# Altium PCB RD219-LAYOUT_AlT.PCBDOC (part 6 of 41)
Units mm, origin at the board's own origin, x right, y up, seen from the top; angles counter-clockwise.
Board outline 209.75 x 159.97 mm, 2 copper layers (TOP, BOTTOM), stack 0 mm thick; 398 components, 199 nets, 1469 pads, 0 vias.
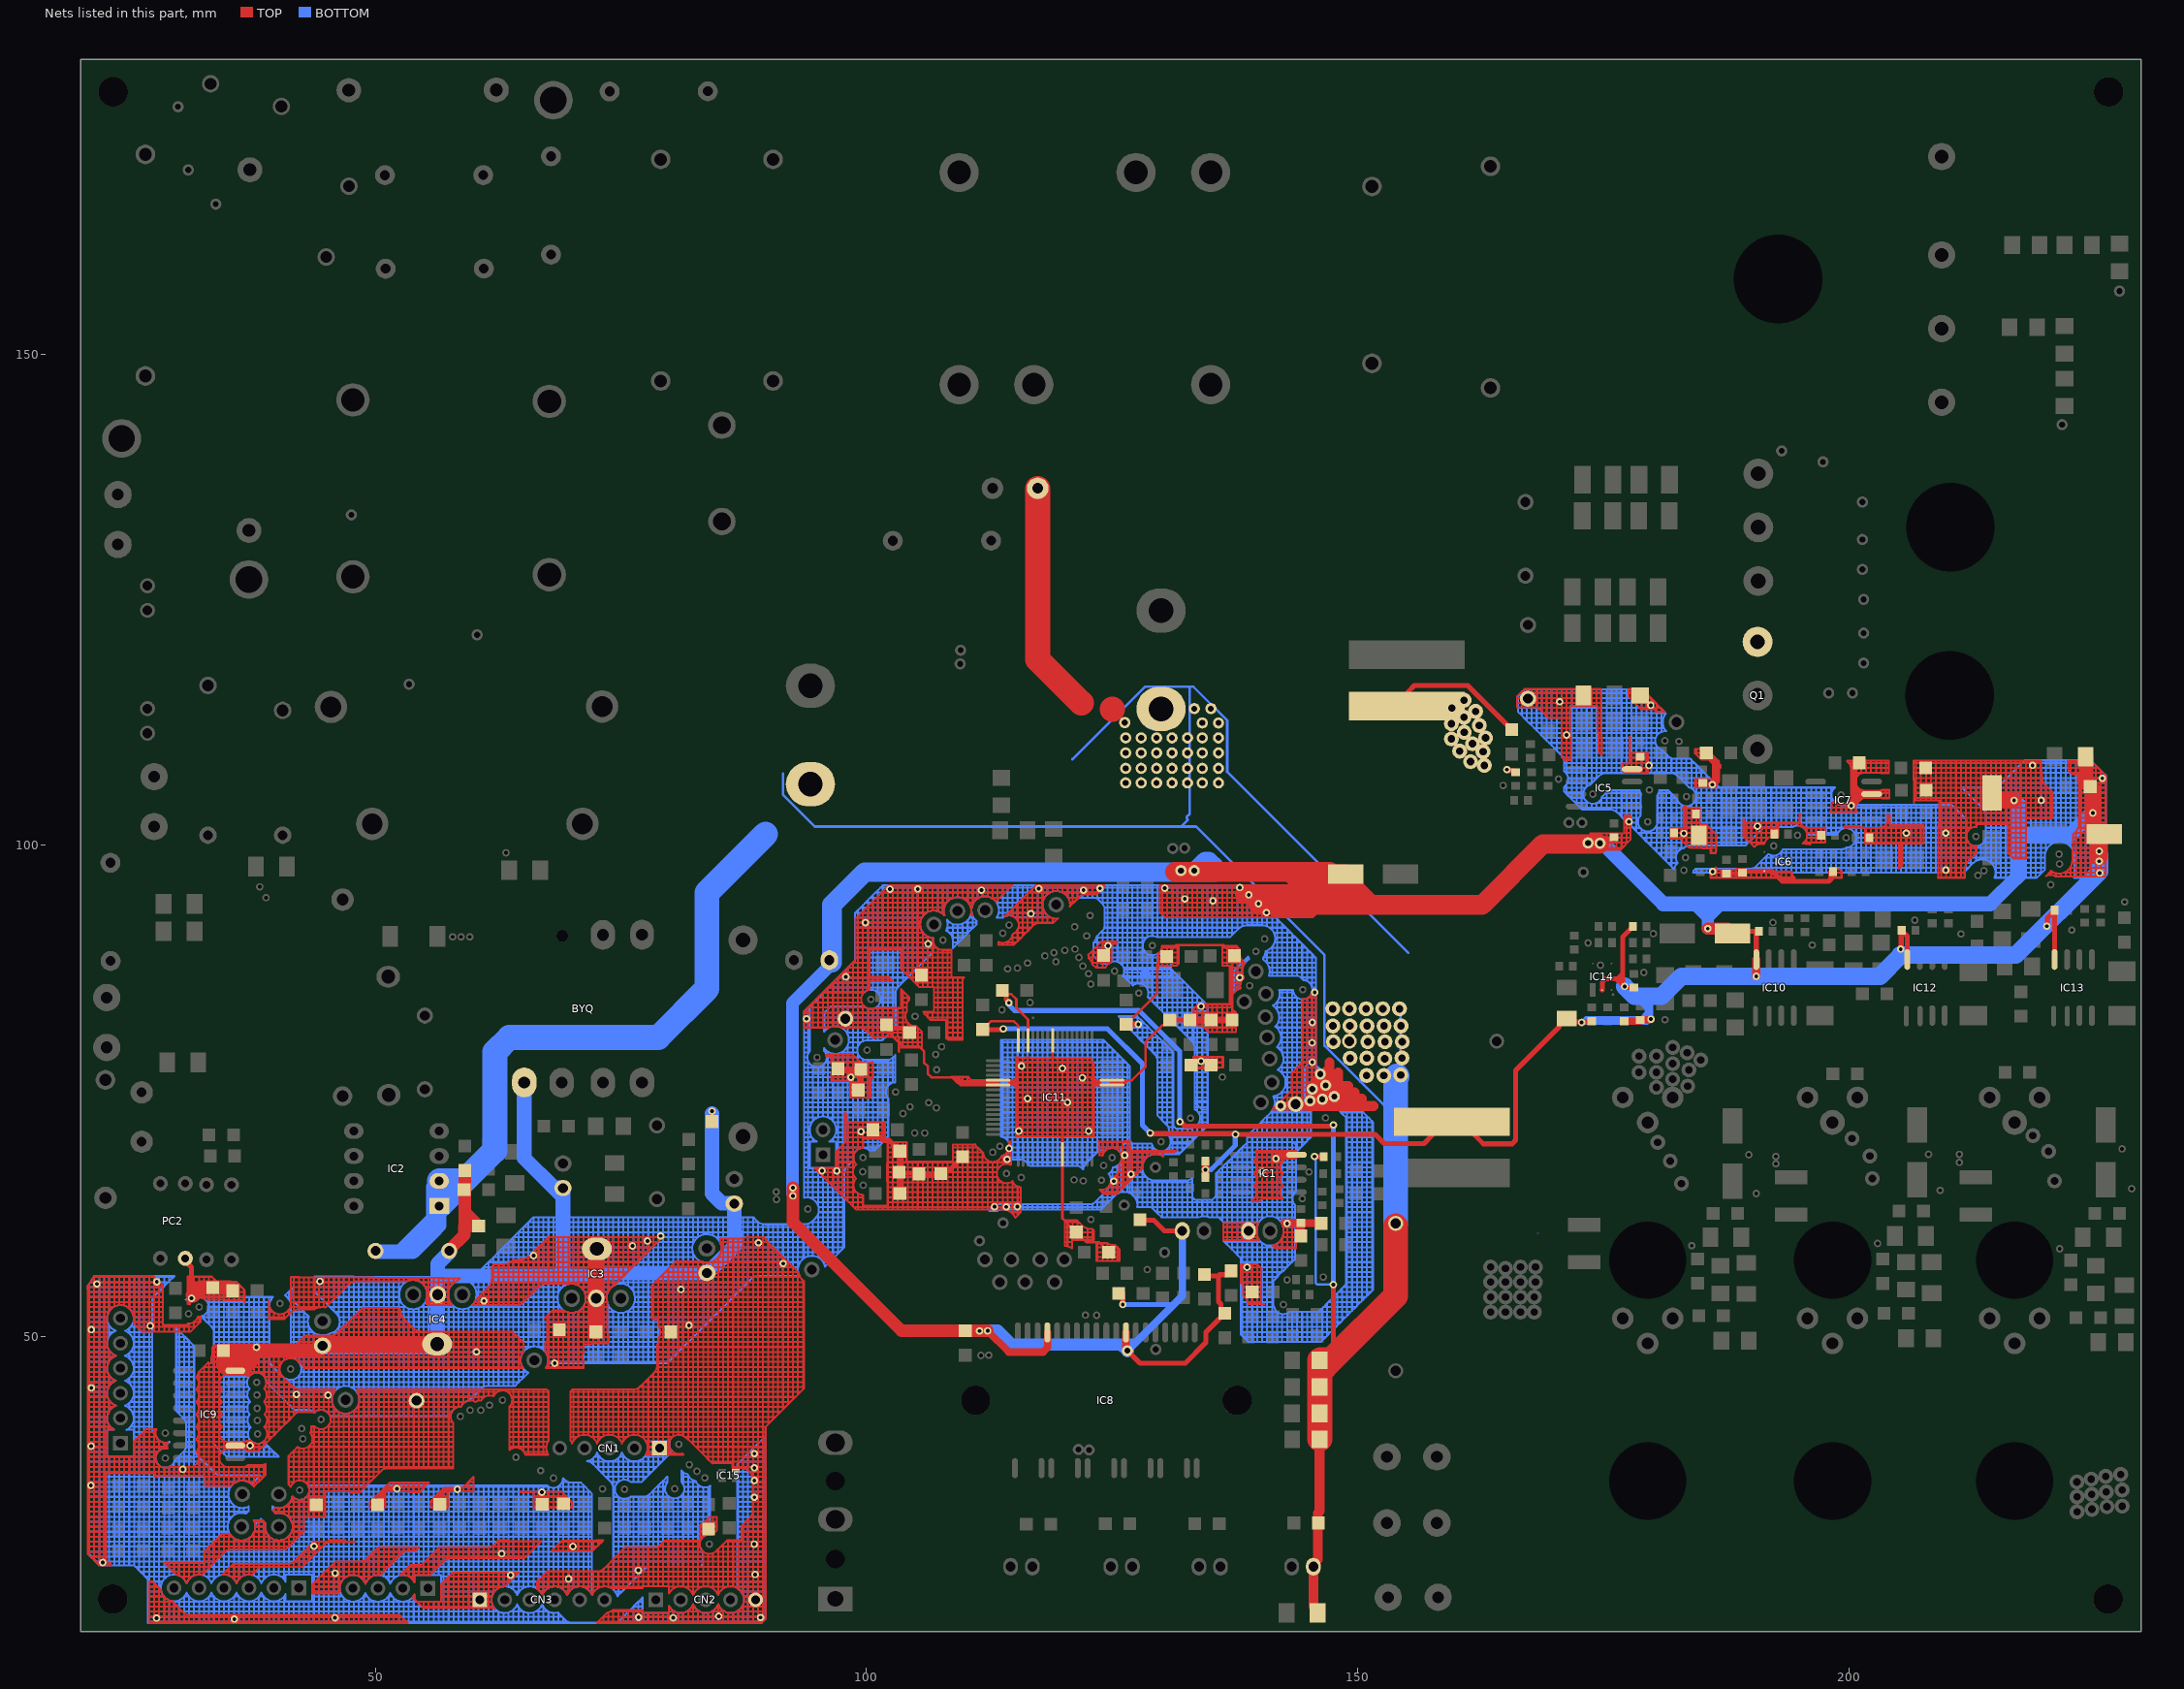
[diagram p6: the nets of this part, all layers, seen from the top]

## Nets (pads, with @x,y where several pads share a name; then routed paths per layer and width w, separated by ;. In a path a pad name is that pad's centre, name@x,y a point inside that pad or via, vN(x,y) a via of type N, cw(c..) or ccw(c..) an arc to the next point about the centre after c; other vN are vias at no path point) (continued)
GND: (continued)
  TOP w0.203: 42.225,33.41 ccw(c42.307,34.389) 42.307,33.407 ccw(c42.307,34.389) 42.733,33.504 ; 42.225,35.368 cw(c42.307,34.389) 42.733,35.275 ; 42.225,35.368 42.225,35.748 ; 42.225,35.748 42.225,36.256 ; 42.225,35.748 42.733,35.748 ; 42.225,36.256 42.733,36.256 ; 42.225,36.256 42.225,36.764 ; 42.225,36.764 42.733,36.764 ; 42.225,36.764 42.225,37.272 ; 42.225,37.272 42.225,37.78 ; 42.225,37.272 42.733,37.272 ; 42.225,37.78 42.225,38.288 ; 42.225,37.78 42.733,37.78 ; 42.225,38.288 42.733,38.288 ; 42.225,38.288 42.225,38.712 ; 42.225,38.712 ccw(c42.625,39.609) 42.728,38.632 ccw(c42.625,39.609) 42.733,38.632 ; 42.225,42.332 cw(c42.376,41.62) 42.376,42.348 ; 42.225,42.332 cw(c42.376,41.62) 42.376,42.348 ; 42.225,42.332 42.225,42.352 ; 42.225,42.352 42.225,42.86 ; 42.225,42.352 42.733,42.352 ; 42.225,42.86 42.225,43.368 ; 42.225,42.86 42.733,42.86 ; 42.225,43.368 pad.@42.225,43.876 ; 42.225,43.368 42.733,43.368 ; pad.@42.225,43.876 42.733,43.876 ; pad.@42.225,43.876 pad.@42.225,44.384 ; pad.@42.225,44.384 42.733,44.384 ; pad.@42.225,44.384 42.225,44.643 ; 42.225,44.643 ccw(c42.354,45.737) 42.354,44.635 ; 42.225,44.643 ccw(c42.354,45.737) 42.354,44.635 ; 42.225,47.423 42.225,47.432 ; 42.225,47.423 42.724,46.924 ; 42.225,47.432 42.225,47.94 ; 42.225,47.432 42.733,47.432 ; 42.225,47.94 42.225,48.448 ; 42.225,47.94 42.733,47.94 ; 42.225,48.448 42.225,48.575 42.225,48.956 ; 42.225,48.448 42.733,48.448 ; 42.225,48.956 42.733,48.956 ; 42.225,48.956 42.225,49.46 ; 42.225,49.46 ccw(c41.322,50.466) 42.229,49.464 ; 42.225,49.46 ccw(c41.322,50.466) 42.229,49.464 ; 42.225,52.805 cw(c42.312,51.456) 42.312,52.808 ; 42.225,52.805 cw(c42.312,51.456) 42.312,52.808 ; 42.225,52.805 42.225,53.02 ; 42.225,53.02 42.225,53.528 ; 42.225,53.02 42.733,53.02 ; 42.225,53.528 42.225,54.036 ; 42.225,53.528 42.733,53.528 ; 42.225,54.036 42.225,54.544 ; 42.225,54.036 42.733,54.036 ; 42.225,54.544 42.225,55.052 ; 42.225,54.544 42.733,54.544 ; 42.225,55.052 42.225,55.56 ; 42.225,55.052 42.733,55.052 ; 42.225,55.56 42.225,56.059 ; 42.225,55.56 42.733,55.56 ; 42.225,56.059 42.733,56.056 ; 42.229,49.464 ccw(c41.322,50.466) 42.277,49.51 cw(c41.322,50.466) 42.229,49.464 ; 42.229,49.464 42.733,49.464 ; 42.239,27.62 42.747,28.128 ; 42.239,27.62 42.733,27.62 ; 42.312,52.808 42.733,52.808 ; 42.354,44.635 42.733,44.635 ; 42.376,42.348 42.733,42.348 ; 42.724,46.924 42.733,46.915 ; 42.724,46.924 42.733,46.924 ; 42.733,20.889 42.733,21.016 ; 42.733,20.889 43.241,20.889 ; 42.733,21.016 42.733,21.524 ; 42.733,21.016 43.241,21.016 ; 42.733,21.524 42.733,21.692 ; 42.733,21.524 43.241,21.524 ; 42.733,21.692 43.241,21.692 ; 42.733,27.112 42.733,27.62 ; 42.733,27.62 43.241,27.62 ; 42.733,30.174 42.733,30.668 ; 42.733,30.174 42.751,30.193 42.751,30.668 ; 42.733,30.668 42.733,31.176 ; 42.733,30.668 42.751,30.668 ; 42.733,31.176 42.733,31.684 ; 42.733,31.176 42.751,31.176 ; 42.733,31.684 43.241,31.684 ; 42.733,31.684 42.733,32.192 ; 42.733,32.192 43.241,32.192 ; 42.733,32.192 42.733,32.7 ; 42.733,32.7 42.733,33.208 ; 42.733,32.7 43.241,32.7 ; 42.733,33.208 43.241,33.208 ; 42.733,33.208 42.733,33.504 ; 42.733,33.504 ccw(c42.307,34.389) 43.023,33.716 ; 42.733,35.275 cw(c42.307,34.389) 42.799,35.24 ; 42.733,35.275 42.733,35.748 ; 42.733,35.748 42.733,36.256 ; 42.733,35.748 43.241,35.748 ; 42.733,36.256 42.733,36.764 ; 42.733,36.256 43.241,36.256 ; 42.733,36.764 42.733,37.272 ; 42.733,36.764 43.241,36.764 ; 42.733,37.272 42.733,37.78 ; 42.733,37.272 43.241,37.272 ; 42.733,37.78 42.733,38.288 ; 42.733,37.78 43.241,37.78 ; 42.733,38.288 43.241,38.288 ; 42.733,38.288 42.733,38.632 ; 42.733,38.632 ccw(c42.625,39.609) 43.177,38.796 ; 42.733,42.348 42.733,42.352 ; 42.733,42.348 43.241,42.348 ; 42.733,42.352 42.733,42.86 ; 42.733,42.352 43.241,42.352 ; 42.733,42.86 42.733,43.368 ; 42.733,42.86 43.241,42.86 ; 42.733,43.368 42.733,43.876 ; 42.733,43.368 43.241,43.368 ; 42.733,43.876 42.733,44.384 ; 42.733,43.876 43.241,43.876 ; 42.733,44.384 42.733,44.635 ; 42.733,44.384 43.241,44.384 ; 42.733,44.635 43.241,44.635 ; 42.733,46.915 42.733,46.924 ; 42.733,46.915 42.81,46.838 43.241,46.838 ; 42.733,46.924 42.733,47.432 ; 42.733,46.924 43.241,46.924 ; 42.733,47.432 42.733,47.94 ; 42.733,47.432 43.241,47.432 ; 42.733,47.94 42.733,48.448 ; 42.733,47.94 43.241,47.94 ; 42.733,48.448 42.733,48.575 42.733,48.956 ; 42.733,48.448 43.241,48.448 ; 42.733,48.956 42.733,49.464 ; 42.733,48.956 43.241,48.956 ; 42.733,49.464 43.241,49.464 ; 42.733,52.808 42.733,53.02 ; 42.733,52.808 43.241,52.808 ; 42.733,53.02 42.733,53.528 ; 42.733,53.02 43.241,53.02 ; 42.733,53.528 42.733,54.036 ; 42.733,53.528 43.241,53.528 ; 42.733,54.036 42.733,54.544 ; 42.733,54.036 43.241,54.036 ; 42.733,54.544 42.733,55.052 ; 42.733,54.544 43.241,54.544 ; 42.733,55.052 42.733,55.56 ; 42.733,55.052 43.241,55.052 ; 42.733,55.56 42.733,56.056 ; 42.733,55.56 43.241,55.56 ; 42.733,56.056 43.241,56.052 ; 42.739,49.972 42.872,50.104 43.241,50.104 ; 42.739,49.972 43.241,49.972 ; 42.747,28.128 43.255,28.636 ; 42.747,28.128 43.241,28.128 ; 42.751,30.668 42.751,31.176 ; 42.751,31.176 42.751,31.666 43.241,31.666 ; 42.799,35.24 cw(c42.307,34.389) 43.228,34.732 ; 42.799,35.24 43.241,35.24 ; 43.023,33.716 ccw(c42.307,34.389) 43.026,33.719 ccw(c42.307,34.389) 43.241,34.083 ; 43.023,33.716 43.241,33.716 ; 43.177,38.796 ccw(c42.625,39.609) 43.241,38.843 ; 43.177,38.796 43.241,38.796 ; 43.228,34.732 cw(c42.307,34.389) 43.241,34.695 ; 43.228,34.732 43.241,34.732 ; 43.241,20.889 43.241,21.016 ; 43.241,20.889 43.749,20.889 ; 43.241,21.016 43.241,21.524 ; 43.241,21.016 43.749,21.016 ; 43.241,21.524 43.241,21.692 ; 43.241,21.524 43.749,21.524 ; 43.241,21.692 43.749,21.692 ; 43.241,27.62 43.241,28.128 ; 43.241,28.128 43.749,28.128 ; 43.241,31.666 43.749,31.666 ; 43.241,31.666 43.241,31.684 ; 43.241,31.684 43.749,31.684 ; 43.241,31.684 43.241,32.192 ; 43.241,32.192 43.749,32.192 ; 43.241,32.192 43.241,32.7 ; 43.241,32.7 43.241,33.208 ; 43.241,32.7 R72.1@43.749,32.7 ; 43.241,33.208 43.241,33.716 ; 43.241,33.208 R72.1@43.749,33.208 ; 43.241,33.716 43.749,33.716 ; 43.241,33.716 43.241,34.083 ; 43.241,34.083 ccw(c42.307,34.389) 43.276,34.224 ; 43.241,34.695 cw(c42.307,34.389) 43.242,34.693 cw(c42.307,34.389) 43.29,34.389 cw(c42.307,34.389) 43.276,34.224 ; 43.241,34.695 43.241,34.732 ; 43.241,34.732 43.749,34.732 ; 43.241,34.732 43.241,35.24 ; 43.241,35.24 43.241,35.748 ; 43.241,35.24 43.749,35.24 ; 43.241,35.748 43.241,36.256 ; 43.241,35.748 43.749,35.748 ; 43.241,36.256 43.749,36.256 ; 43.241,36.256 43.241,36.764 ; 43.241,36.764 43.749,36.764 ; 43.241,36.764 43.241,37.272 ; 43.241,37.272 43.241,37.78 ; 43.241,37.272 43.749,37.272 ; 43.241,37.78 43.749,37.78 ; 43.241,37.78 43.241,38.288 ; 43.241,38.288 43.241,38.796 ; 43.241,38.288 43.749,38.288 ; 43.241,38.796 43.749,38.796 ; 43.241,38.796 43.241,38.843 ; 43.241,38.843 ccw(c42.625,39.609) 43.244,38.845 ccw(c42.625,39.609) 43.559,39.304 ; 43.241,42.348 43.749,42.348 ; 43.241,42.348 43.241,42.352 ; 43.241,42.352 43.749,42.352 ; 43.241,42.352 43.241,42.86 ; 43.241,42.86 43.749,42.86 ; 43.241,42.86 43.241,43.368 ; 43.241,43.368 43.749,43.368 ; 43.241,43.368 43.241,43.876 ; 43.241,43.876 43.749,43.876 ; 43.241,43.876 43.241,44.384 ; 43.241,44.384 43.749,44.384 ; 43.241,44.384 43.241,44.635 ; 43.241,44.635 43.749,44.635 ; 43.241,46.838 43.241,46.924 ; 43.241,46.838 43.749,46.838 ; 43.241,46.924 43.241,47.432 ; 43.241,46.924 43.749,46.924 ; 43.241,47.432 43.241,47.94 ; 43.241,47.432 43.749,47.432 ; 43.241,47.94 43.241,48.448 ; 43.241,47.94 43.749,47.94 ; 43.241,48.448 43.241,48.575 43.241,48.956 ; 43.241,48.448 43.749,48.448 ; 43.241,48.956 43.241,49.464 ; 43.241,48.956 43.749,48.956 ; 43.241,49.464 43.241,49.972 ; 43.241,49.464 43.749,49.464 ; 43.241,49.972 43.241,50.104 ; 43.241,49.972 43.749,49.972 ; 43.241,50.104 43.749,50.104 ; 43.241,52.808 43.749,52.808 ; 43.241,52.808 43.241,53.02 ; 43.241,53.02 43.749,53.02 ; 43.241,53.02 43.241,53.528 ; 43.241,53.528 43.749,53.528 ; 43.241,53.528 43.241,54.036 ; 43.241,54.036 43.241,54.544 ; 43.241,54.036 43.749,54.036 ; 43.241,54.544 43.241,55.052 ; 43.241,54.544 43.749,54.544 ; 43.241,55.052 43.241,55.56 ; 43.241,55.052 43.749,55.052 ; 43.241,55.56 43.241,56.052 ; 43.241,55.56 43.749,55.56 ; 43.241,56.052 43.749,56.049 ; 43.255,28.636 pad.@43.749,28.636 ; 43.255,28.636 43.763,29.144 ; 43.276,34.224 43.749,34.224 ; 43.435,40.32 ccw(c42.513,40.658) 43.48,40.828 ; 43.435,40.32 43.749,40.32 ; 43.467,40.891 cw(c42.513,40.658) 43.48,40.828 ; 43.467,40.891 43.749,40.891 ; 43.48,40.828 43.749,40.828 ; 43.559,39.304 ccw(c42.625,39.609) 43.56,39.305 ccw(c42.625,39.609) 43.608,39.609 ccw(c42.625,39.609) 43.587,39.812 ; 43.559,39.304 43.749,39.304 ; 43.577,24.064 43.749,24.064 ; 43.577,24.064 43.577,24.572 ; 43.577,24.064 43.577,23.896 43.749,23.896 ; 43.577,24.572 43.749,24.572 ; 43.577,24.572 43.577,24.766 43.749,24.939 ; 43.587,39.812 43.749,39.812 ; 43.749,20.889 43.749,21.016 ; 43.749,20.889 44.257,20.889 ; 43.749,21.016 43.749,21.524 ; 43.749,21.016 44.257,21.016 ; 43.749,21.524 43.749,21.692 ; 43.749,21.524 44.257,21.524 ; 43.749,21.692 44.257,21.692 ; 43.749,23.896 43.749,24.064 ; 43.749,23.896 44.257,23.896 ; 43.749,24.064 43.749,24.572 ; 43.749,24.064 44.257,24.064 ; 43.749,24.572 43.749,24.939 ; 43.749,24.572 44.257,24.572 ; 43.749,24.939 43.89,25.08 ; 43.749,28.128 pad.@43.749,28.636 ; pad.@43.749,28.636 44.257,28.636 ; 43.749,31.666 44.257,31.666 ; 43.749,31.666 43.749,31.684 ; 43.749,31.684 44.257,31.684 ; 43.749,31.684 43.749,32.192 ; 43.749,32.192 R72.1@43.749,32.7 ; 43.749,32.192 44.257,32.192 ; R72.1@43.749,32.7 R72.1@44.257,32.7 ; R72.1@43.749,32.7 R72.1@43.749,33.208 ; R72.1@43.749,33.208 43.749,33.716 ; R72.1@43.749,33.208 R72.1@44.257,33.208 ; 43.749,33.716 43.749,34.224 ; 43.749,33.716 44.257,33.716 ; 43.749,34.224 44.257,34.224 ; 43.749,34.224 43.749,34.732 ; 43.749,34.732 43.749,35.24 ; 43.749,34.732 44.257,34.732 ; 43.749,35.24 43.749,35.748 ; 43.749,35.24 44.257,35.24 ; 43.749,35.748 43.749,36.256 ; 43.749,35.748 44.257,35.748 ; 43.749,36.256 44.257,36.256 ; 43.749,36.256 43.749,36.764 ; 43.749,36.764 44.257,36.764 ; 43.749,36.764 43.749,37.272 ; 43.749,37.272 43.749,37.78 ; 43.749,37.272 44.257,37.272 ; 43.749,37.78 43.749,38.288 ; 43.749,37.78 44.257,37.78 ; 43.749,38.288 43.749,38.796 ; 43.749,38.288 44.257,38.288 ; 43.749,38.796 43.749,39.304 ; 43.749,38.796 44.257,38.796 ; 43.749,39.304 43.749,39.812 ; 43.749,39.304 44.257,39.304 ; 43.749,39.812 43.749,40.32 ; 43.749,39.812 44.257,39.812 ; 43.749,40.32 44.257,40.32 ; 43.749,40.32 43.749,40.828 ; 43.749,40.828 43.749,40.891 ; 43.749,40.828 43.862,40.828 ; 43.749,40.891 43.792,40.891 ; 43.749,42.348 43.749,42.352 ; 43.749,42.352 43.749,42.86 ; 43.749,42.86 43.749,43.368 ; 43.749,42.86 44.257,42.86 ; 43.749,43.368 43.749,43.876 ; 43.749,43.368 44.257,43.368 ; 43.749,43.876 44.257,43.876 ; 43.749,43.876 43.749,44.384 ; 43.749,44.384 44.257,44.384 ; 43.749,44.384 43.749,44.635 ; 43.749,44.635 44.257,44.635 ; 43.749,46.838 43.749,46.924 ; 43.749,46.838 44.257,46.838 ; 43.749,46.924 43.749,47.432 ; 43.749,46.924 44.257,46.924 ; 43.749,47.432 43.749,47.94 ; 43.749,47.432 44.257,47.432 ; 43.749,47.94 43.749,48.448 ; 43.749,47.94 44.257,47.94 ; 43.749,48.448 43.749,48.575 43.749,48.956 ; 43.749,48.448 EC6.2@44.257,48.448 ; 43.749,48.956 EC6.2@44.257,48.956 ; 43.749,48.956 43.749,49.464 ; 43.749,49.464 43.749,49.972 ; 43.749,49.464 EC6.2@44.257,49.464 ; 43.749,49.972 43.749,50.104 ; 43.749,49.972 44.257,49.972 ; 43.749,50.104 44.257,50.104 ; 43.749,52.808 43.749,53.02 ; 43.749,52.808 43.842,52.808 ; 43.749,53.02 44.257,53.02 ; 43.749,53.02 43.749,53.528 ; 43.749,53.528 44.257,53.528 ; 43.749,53.528 43.749,54.036 ; 43.749,54.036 43.749,54.544 ; 43.749,54.036 44.257,54.036 ; 43.749,54.544 43.749,55.052 ; 43.749,54.544 44.257,54.544 ; 43.749,55.052 43.749,55.56 ; 43.749,55.052 44.257,55.052 ; 43.749,55.56 43.749,56.049 ; 43.749,55.56 pad.@44.257,55.56 ; 43.749,56.049 44.257,56.046 ; 43.763,29.144 43.782,29.162 44.257,29.162 ; 43.763,29.144 44.257,29.144 ; 43.792,40.891 ccw(c44.482,41.59) 43.862,40.828 ; 43.842,52.808 cw(c44.575,51.583) 44.253,52.974 cw(c44.575,51.583) 44.257,52.974 ; 43.89,25.08 44.257,25.447 ; 43.89,25.08 44.257,25.08 ; 44.257,20.889 44.257,21.016 ; 44.257,20.889 44.765,20.889 ; 44.257,21.016 44.257,21.524 ; 44.257,21.016 44.765,21.016 ; 44.257,21.524 44.257,21.692 ; 44.257,21.524 44.765,21.524 ; 44.257,21.692 44.765,21.692 ; 44.257,23.896 44.257,24.064 ; 44.257,23.896 44.765,23.896 ; 44.257,24.064 44.257,24.572 ; 44.257,24.064 44.765,24.064 ; 44.257,24.572 44.257,25.08 ; 44.257,24.572 44.765,24.572 ; 44.257,25.08 44.257,25.447 ; 44.257,25.08 44.765,25.08 ; 44.257,25.447 44.398,25.588 ; 44.257,28.636 44.257,29.144 ; 44.257,29.144 44.765,29.144 ; 44.257,29.144 44.257,29.162 ; 44.257,29.162 44.765,29.162 ; 44.257,31.666 44.765,31.666 ; 44.257,31.666 44.257,31.684 ; 44.257,31.684 44.765,31.684 ; 44.257,31.684 44.257,32.192 ; 44.257,32.192 44.765,32.192 ; 44.257,32.192 R72.1@44.257,32.7 ; R72.1@44.257,32.7 44.765,32.7 ; R72.1@44.257,32.7 R72.1@44.257,33.208 ; R72.1@44.257,33.208 44.257,33.716 ; R72.1@44.257,33.208 44.765,33.208 ; 44.257,33.716 44.257,34.224 ; 44.257,33.716 44.765,33.716 ; 44.257,34.224 44.765,34.224 ; 44.257,34.224 44.257,34.732 ; 44.257,34.732 44.257,35.24 ; 44.257,34.732 44.765,34.732 ; 44.257,35.24 44.257,35.748 ; 44.257,35.24 44.765,35.24 ; 44.257,35.748 44.257,36.256 ; 44.257,35.748 44.765,35.748 ; 44.257,36.256 44.765,36.256 ; 44.257,36.256 44.257,36.764 ; 44.257,36.764 44.765,36.764 ; 44.257,36.764 44.257,37.272 ; 44.257,37.272 44.257,37.78 ; 44.257,37.272 44.765,37.272 ; 44.257,37.78 44.765,37.78 ; 44.257,37.78 44.257,38.288 ; 44.257,38.288 44.257,38.796 ; 44.257,38.288 44.765,38.288 ; 44.257,38.796 44.257,39.304 ; 44.257,38.796 44.765,38.796 ; 44.257,39.304 44.257,39.812 ; 44.257,39.304 44.765,39.304 ; 44.257,39.812 44.257,40.32 ; 44.257,39.812 44.765,39.812 ; 44.257,40.32 44.765,40.32 ; 44.257,42.546 cw(c44.482,41.59) 44.261,42.547 cw(c44.482,41.59) 44.765,42.531 ; 44.257,42.546 44.257,42.86 ; 44.257,42.86 44.257,43.368 ; 44.257,42.86 44.765,42.86 ; 44.257,43.368 44.257,43.876 ; 44.257,43.368 44.765,43.368 ; 44.257,43.876 44.257,44.384 ; 44.257,43.876 44.765,43.876 ; 44.257,44.384 44.257,44.635 ; 44.257,44.384 44.765,44.384 ; 44.257,44.635 44.765,44.635 ; 44.257,46.838 44.257,46.924 ; 44.257,46.838 44.765,46.838 ; 44.257,46.924 44.257,47.432 ; 44.257,46.924 44.765,46.924 ; 44.257,47.432 44.257,47.94 ; 44.257,47.432 44.765,47.432 ; 44.257,47.94 EC6.2@44.257,48.448 ; 44.257,47.94 44.765,47.94 ; EC6.2@44.257,48.448 44.257,48.806 EC6.2@44.257,48.956 ; EC6.2@44.257,48.448 EC6.2@44.765,48.448 ; EC6.2@44.257,48.956 44.407,48.956 EC6.2@44.765,48.956 ; EC6.2@44.257,48.956 EC6.2@44.257,49.464 ; EC6.2@44.257,49.464 44.257,49.972 ; EC6.2@44.257,49.464 EC6.2@44.765,49.464 ; 44.257,49.972 44.257,50.104 ; 44.257,49.972 44.765,49.972 ; 44.257,50.104 44.765,50.104 ; 44.257,52.974 cw(c44.575,51.583) 44.575,53.01 44.702,53.01 cw(c44.702,51.583) 44.765,53.009 ; 44.257,52.974 44.257,53.02 ; 44.257,53.02 44.765,53.02 ; 44.257,53.02 44.257,53.528 ; 44.257,53.528 44.765,53.528 ; 44.257,53.528 44.257,54.036 ; 44.257,54.036 44.257,54.544 ; 44.257,54.036 44.765,54.036 ; 44.257,54.544 44.257,55.052 ; 44.257,54.544 44.765,54.544 ; 44.257,55.052 pad.@44.257,55.56 ; 44.257,55.052 44.765,55.052 ; pad.@44.257,55.56 44.257,56.046 ; pad.@44.257,55.56 44.765,55.56 ; 44.257,56.046 44.37,56.045 44.765,56.042 ; 44.398,25.588 44.765,25.588 ; 44.398,25.588 44.765,25.955 ; 44.765,20.889 44.765,21.016 ; 44.765,20.889 45.273,20.889 ; 44.765,21.016 44.765,21.524 ; 44.765,21.016 45.273,21.016 ; 44.765,21.524 44.765,21.692 ; 44.765,21.524 45.273,21.524 ; 44.765,21.692 45.273,21.692 ; 44.765,23.896 44.765,24.064 ; 44.765,23.896 45.273,23.896 ; 44.765,24.064 44.765,24.572 ; 44.765,24.064 45.273,24.064 ; 44.765,24.572 44.765,25.08 ; 44.765,24.572 45.273,24.572 ; 44.765,25.08 44.765,25.588 ; 44.765,25.08 45.273,25.08 ; 44.765,25.588 44.765,25.955 ; 44.765,25.588 45.273,25.588 ; 44.765,25.955 44.906,26.096 ; 44.765,28.777 44.765,29.144 ; 44.765,28.777 44.885,28.897 ; 44.765,29.144 45.273,29.144 ; 44.765,29.144 44.765,29.162 ; 44.765,29.162 45.255,29.162 45.255,29.289 45.273,29.289 ; 44.765,31.666 44.91,31.666 44.91,31.684 ; 44.765,31.666 44.765,31.684 ; 44.765,31.684 44.765,32.192 ; 44.765,31.684 44.91,31.684 ; 44.765,32.192 44.91,32.192 ; 44.765,32.192 44.765,32.7 ; 44.765,32.7 44.765,33.208 ; 44.765,32.7 44.91,32.7 ; 44.765,33.208 44.765,33.716 ; 44.765,33.208 44.91,33.208 ; 44.765,33.716 44.765,34.224 ; 44.765,33.716 44.91,33.716 ; 44.765,34.224 44.91,34.224 ; 44.765,34.224 44.765,34.732 ; 44.765,34.732 44.765,35.24 ; 44.765,34.732 45.273,34.732 ; 44.765,35.24 44.765,35.748 ; 44.765,35.24 45.273,35.24 ; 44.765,35.748 44.765,36.256 ; 44.765,35.748 45.273,35.748 ; 44.765,36.256 45.273,36.256 ; 44.765,36.256 44.765,36.764 ; 44.765,36.764 45.273,36.764 ; 44.765,36.764 44.765,37.272 ; 44.765,37.272 44.765,37.78 ; 44.765,37.272 45.273,37.272 ; 44.765,37.78 44.765,38.288 ; 44.765,37.78 45.273,37.78 ; 44.765,38.288 44.765,38.796 ; 44.765,38.288 45.273,38.288 ; 44.765,38.796 44.765,39.304 ; 44.765,38.796 45.273,38.796 ; 44.765,39.304 44.765,39.812 ; 44.765,39.304 45.273,39.304 ; 44.765,39.812 44.765,40.32 ; 44.765,39.812 45.273,39.812 ; 44.765,40.32 45.273,40.32 ; 44.765,40.32 44.765,40.649 ; 44.765,40.649 ccw(c44.482,41.59) 45.101,40.826 ccw(c44.482,41.59) 45.103,40.828 ; 44.765,42.531 44.765,42.86 ; 44.765,42.86 44.765,43.368 ; 44.765,42.86 45.273,42.86 ; 44.765,43.368 44.765,43.876 ; 44.765,43.368 45.273,43.368 ; 44.765,43.876 pad.@45.273,43.876 ; 44.765,43.876 44.765,44.384 ; 44.765,44.384 44.765,44.635 ; 44.765,44.384 pad.@45.273,44.384 ; 44.765,44.635 45.273,44.635 ; 44.765,46.838 45.273,46.838 ; 44.765,46.838 44.765,46.924 ; 44.765,46.924 45.273,46.924 ; 44.765,46.924 44.765,47.432 ; 44.765,47.432 45.273,47.432 ; 44.765,47.432 44.765,47.94 ; 44.765,47.94 45.273,47.94 ; 44.765,47.94 EC6.2@44.765,48.448 ; EC6.2@44.765,48.448 45.273,48.448 ; EC6.2@44.765,48.448 EC6.2@44.765,48.956 ; EC6.2@44.765,48.956 EC6.2@45.273,48.956 ; EC6.2@44.765,48.956 44.765,49.112 EC6.2@44.765,49.464 ; EC6.2@44.765,49.464 EC6.2@45.273,49.464 ; EC6.2@44.765,49.464 44.765,49.972 ; 44.765,49.972 45.273,49.972 ; 44.765,49.972 44.765,50.104 ; 44.765,50.104 45.273,50.104 ; 44.765,53.009 44.765,53.02 ; 44.765,53.02 44.765,53.528 ; 44.765,53.528 45.273,53.528 ; 44.765,53.528 44.765,54.036 ; 44.765,54.036 44.765,54.544 ; 44.765,54.036 45.273,54.036 ; 44.765,54.544 44.765,55.052 ; 44.765,54.544 45.273,54.544 ; 44.765,55.052 44.765,55.56 ; 44.765,55.052 45.273,55.052 ; 44.765,55.56 45.273,55.56 ; 44.765,55.56 44.765,56.042 ; 44.765,56.042 45.273,56.039 ; 44.885,28.897 cw(c45.4,28.382) 45.273,29.099 ; 44.885,28.897 cw(c45.4,28.382) 45.273,29.099 ; 44.906,26.096 45.273,26.463 ; 44.906,26.096 45.273,26.096 ; 44.91,32.192 44.91,32.7 ; 44.91,32.7 44.91,33.208 ; 44.91,33.208 44.91,33.716 ; 44.91,33.716 44.91,34.224 ; 44.91,34.224 44.91,34.282 45.273,34.282 ; 45.103,40.828 45.273,40.828 ; 45.273,20.889 45.273,21.016 ; 45.273,20.889 45.781,20.889 ; 45.273,21.016 45.273,21.524 ; 45.273,21.016 45.781,21.016 ; 45.273,21.524 45.273,21.692 ; 45.273,21.524 pad.@45.781,21.524 ; 45.273,21.692 pad.@45.781,21.692 ; 45.273,23.896 45.781,23.896 ; 45.273,23.896 45.273,24.064 ; 45.273,24.064 45.781,24.064 ; 45.273,24.064 45.273,24.572 ; 45.273,24.572 45.781,24.572 ; 45.273,24.572 45.273,25.08 ; 45.273,25.08 45.781,25.08 ; 45.273,25.08 45.273,25.588 ; 45.273,25.588 45.273,26.096 ; 45.273,25.588 pad.@45.781,25.588 ; 45.273,26.096 45.273,26.463 ; 45.273,26.096 pad.@45.781,26.096 ; 45.273,26.463 45.414,26.604 ; 45.273,29.099 cw(c45.4,28.382) 45.4,29.111 ; 45.273,29.099 cw(c45.4,28.382) 45.4,29.111 ; 45.273,29.099 45.273,29.144 ; 45.273,29.144 45.273,29.289 ; 45.273,29.144 45.781,29.144 ; 45.273,29.289 45.781,29.289 ; 45.273,34.282 45.781,34.282 ; 45.273,34.282 45.273,34.732 ; 45.273,34.732 45.273,35.24 ; 45.273,34.732 45.781,34.732 ; 45.273,35.24 45.273,35.748 ; 45.273,35.24 45.781,35.24 ; 45.273,35.748 45.273,36.256 ; 45.273,35.748 45.781,35.748 ; 45.273,36.256 45.781,36.256 ; 45.273,36.256 45.273,36.764 ; 45.273,36.764 45.781,36.764 ; 45.273,36.764 45.273,37.272 ; 45.273,37.272 45.273,37.78 ; 45.273,37.272 45.781,37.272 ; 45.273,37.78 45.781,37.78 ; 45.273,37.78 45.273,38.288 ; 45.273,38.288 45.273,38.796 ; 45.273,38.288 45.781,38.288 ; 45.273,38.796 45.273,39.304 ; 45.273,38.796 45.781,38.796 ; 45.273,39.304 45.273,39.812 ; 45.273,39.304 45.781,39.304 ; 45.273,39.812 45.273,40.32 ; 45.273,39.812 45.781,39.812 ; 45.273,40.32 45.781,40.32 ; 45.273,40.32 45.273,40.828 ; 45.273,40.828 45.781,40.828 ; 45.273,42.173 cw(c44.482,41.59) 45.277,42.168 cw(c44.482,41.59) 45.432,41.844 ; 45.273,42.173 45.273,42.352 ; 45.273,42.352 45.273,42.86 ; 45.273,42.352 45.781,42.352 ; 45.273,42.86 45.273,43.368 ; 45.273,42.86 45.774,42.86 ; 45.273,43.368 pad.@45.273,43.876 ; 45.273,43.368 45.593,43.368 ; pad.@45.273,43.876 pad.@45.273,44.384 ; pad.@45.273,43.876 45.61,43.876 ; pad.@45.273,44.384 45.781,44.384 ; pad.@45.273,44.384 45.273,44.635 ; 45.273,44.635 45.781,44.635 ; 45.273,46.838 45.273,46.924 ; 45.273,46.838 45.781,46.838 ; 45.273,46.924 45.273,47.432 ; 45.273,46.924 45.781,46.924 ; 45.273,47.432 45.273,47.94 ; 45.273,47.432 45.781,47.432 ; 45.273,47.94 45.273,48.448 ; 45.273,47.94 45.781,47.94 ; 45.273,48.448 EC6.2@45.273,48.956 ; 45.273,48.448 45.781,48.448 ; EC6.2@45.273,48.956 45.781,48.956 ; EC6.2@45.273,48.956 45.273,49.112 EC6.2@45.273,49.464 ; EC6.2@45.273,49.464 45.273,49.972 ; EC6.2@45.273,49.464 45.781,49.464 ; 45.273,49.972 45.273,50.104 ; 45.273,49.972 45.781,49.972 ; 45.273,50.104 45.337,50.104 ; 45.273,53.304 45.273,53.528 ; 45.273,53.304 45.781,53.812 ; 45.273,53.528 45.273,54.036 ; 45.273,54.036 45.273,54.544 ; 45.273,54.036 45.781,54.036 ; 45.273,54.544 45.273,55.052 ; 45.273,54.544 45.781,54.544 ; 45.273,55.052 45.273,55.56 ; 45.273,55.052 45.781,55.052 ; 45.273,55.56 45.273,56.039 ; 45.273,55.56 45.781,55.56 ; 45.273,56.039 45.781,56.036 ; 45.337,50.104 ccw(c45.337,51.456) 45.777,50.178 ; 45.337,50.104 ccw(c45.337,51.456) 45.777,50.178 ; 45.4,29.111 45.781,29.111 ; 45.414,26.604 45.781,26.971 ; 45.414,26.604 45.781,26.604 ; 45.432,41.336 ccw(c44.482,41.59) 45.465,41.59 ccw(c44.482,41.59) 45.436,41.828 ccw(c44.482,41.59) 45.432,41.844 ; 45.432,41.336 45.781,41.336 ; 45.432,41.844 45.781,41.844 ; 45.593,43.368 ccw(c46.979,43.576) 45.774,42.86 ; 45.593,43.368 cw(c46.979,43.576) 45.61,43.876 ; 45.61,43.876 cw(c46.979,43.576) 45.781,44.304 ; 45.774,42.86 ccw(c46.979,43.576) 45.781,42.849 ; 45.777,50.178 ccw(c45.337,51.456) 45.781,50.18 ; 45.777,50.178 ccw(c45.337,51.456) 45.781,50.18 ; 45.781,20.889 45.781,21.016 ; 45.781,20.889 46.289,20.889 ; 45.781,21.016 pad.@45.781,21.524 ; 45.781,21.016 46.289,21.016 ; pad.@45.781,21.524 pad.@45.781,21.692 ; pad.@45.781,21.524 46.289,21.524 ; pad.@45.781,21.692 46.289,21.692 ; 45.781,23.896 45.781,24.064 ; 45.781,23.896 46.214,23.896 46.289,23.971 ; 45.781,24.064 46.289,24.064 ; 45.781,24.064 45.781,24.572 ; 45.781,24.572 46.289,24.572 ; 45.781,24.572 45.781,25.08 ; 45.781,25.08 46.289,25.08 ; 45.781,25.08 pad.@45.781,25.588 ; pad.@45.781,25.588 46.289,25.588 ; pad.@45.781,25.588 pad.@45.781,26.096 ; pad.@45.781,26.096 45.781,26.604 ; pad.@45.781,26.096 46.289,26.096 ; 45.781,26.604 45.781,26.971 ; 45.781,26.604 46.289,26.604 ; 45.781,26.971 45.922,27.112 ; 45.781,29.111 45.781,29.144 ; 45.781,29.111 46.289,29.111 ; 45.781,29.144 45.781,29.289 ; 45.781,29.144 46.289,29.144 ; 45.781,29.289 46.289,29.289 ; 45.781,34.282 46.289,34.282 ; 45.781,34.282 45.781,34.732 ; 45.781,34.732 45.781,35.24 ; 45.781,34.732 46.289,34.732 ; 45.781,35.24 45.781,35.748 ; 45.781,35.24 46.289,35.24 ; 45.781,35.748 45.781,36.256 ; 45.781,35.748 46.289,35.748 ; 45.781,36.256 45.781,36.764 ; 45.781,36.256 46.289,36.256 ; 45.781,36.764 46.289,36.764 ; 45.781,36.764 45.781,37.272 ; 45.781,37.272 45.781,37.78 ; 45.781,37.272 46.289,37.272 ; 45.781,37.78 45.781,38.288 ; 45.781,37.78 46.289,37.78 ; 45.781,38.288 45.781,38.796 ; 45.781,38.288 46.289,38.288 ; 45.781,38.796 45.781,39.304 ; 45.781,38.796 46.289,38.796 ; 45.781,39.304 45.781,39.812 ; 45.781,39.304 46.289,39.304 ; 45.781,39.812 45.781,40.32 ; 45.781,39.812 46.289,39.812 ; 45.781,40.32 45.781,40.828 ; 45.781,40.32 46.289,40.32 ; 45.781,40.828 45.781,41.336 ; 45.781,40.828 46.289,40.828 ; 45.781,41.336 45.781,41.844 ; 45.781,41.336 46.289,41.336 ; 45.781,41.844 45.781,42.352 ; 45.781,41.844 46.289,41.844 ; 45.781,42.352 46.289,42.352 ; 45.781,42.352 45.781,42.849 ; 45.781,44.304 cw(c46.979,43.576) 45.833,44.384 ; 45.781,44.304 45.781,44.384 ; 45.781,44.384 45.781,44.635 ; 45.781,44.384 45.833,44.384 ; 45.781,44.635 45.949,44.635 45.949,44.527 ; 45.781,46.838 46.289,46.838 ; 45.781,46.838 45.781,46.924 ; 45.781,46.924 46.289,46.924 ; 45.781,46.924 45.781,47.432 ; 45.781,47.432 46.289,47.432 ; 45.781,47.432 45.781,47.94 ; 45.781,47.94 46.289,47.94 ; 45.781,47.94 45.781,48.448 ; 45.781,48.448 46.289,48.448 ; 45.781,48.448 45.781,48.956 ; 45.781,48.956 46.289,48.956 ; 45.781,48.956 45.781,49.112 45.781,49.464 ; 45.781,49.464 46.289,49.464 ; 45.781,49.464 45.781,49.972 ; 45.781,49.972 46.289,49.972 ; 45.781,49.972 45.781,50.18 ; 45.781,50.18 ccw(c45.337,51.456) 46.272,50.48 ; 45.781,50.18 ccw(c45.337,51.456) 46.272,50.48 ; 45.781,53.812 45.781,54.036 ; 45.781,53.812 46.005,54.036 ; 45.781,54.036 45.781,54.544 ; 45.781,54.036 46.005,54.036 ; 45.781,54.544 45.781,55.052 ; 45.781,54.544 46.289,54.544 ; 45.781,55.052 45.781,55.56 ; 45.781,55.052 46.289,55.052 ; 45.781,55.56 45.781,56.036 ; 45.781,55.56 46.289,55.56 ; 45.781,56.036 46.289,56.032 ; 45.833,44.384 cw(c46.979,43.576) 45.949,44.527 ; 45.922,27.112 46.289,27.112 ; 45.922,27.112 45.956,27.145 46.289,27.145 ; 46.005,54.036 46.289,54.32 ; 46.272,50.48 ccw(c45.337,51.456) 46.289,50.497 ; 46.272,50.48 ccw(c45.337,51.456) 46.289,50.497 ; 46.272,50.48 46.289,50.48 ; 46.289,20.889 46.797,20.889 ; 46.289,20.889 46.289,21.016 ; 46.289,21.016 46.797,21.016 ; 46.289,21.016 46.289,21.524 ; 46.289,21.524 46.289,21.692 ; 46.289,21.524 46.797,21.524 ; 46.289,21.692 46.797,21.692 ; 46.289,23.971 46.289,24.064 ; 46.289,23.971 46.382,24.064 ; 46.289,24.064 46.382,24.064 ; 46.289,24.064 46.289,24.572 ; 46.289,24.572 46.289,25.08 ; 46.289,24.572 46.389,24.572 ; 46.289,25.08 46.289,25.588 ; 46.289,25.08 46.562,25.08 ; 46.289,25.588 46.797,25.588 ; 46.289,25.588 46.289,26.096 ; 46.289,26.096 46.289,26.604 ; 46.289,26.096 46.797,26.096 ; 46.289,26.604 46.289,27.112 ; 46.289,26.604 46.797,26.604 ; 46.289,27.112 46.797,27.112 ; 46.289,27.112 46.289,27.145 ; 46.289,27.145 46.797,27.145 ; 46.289,29.111 46.797,29.111 ; 46.289,29.111 46.289,29.144 ; 46.289,29.144 46.797,29.144 ; 46.289,29.144 46.289,29.289 ; 46.289,29.289 46.797,29.289 ; 46.289,34.282 46.289,34.732 ; 46.289,34.282 46.797,34.282 ; 46.289,34.732 46.289,35.24 ; 46.289,34.732 46.797,34.732 ; 46.289,35.24 46.289,35.748 ; 46.289,35.24 46.797,35.24 ; 46.289,35.748 46.289,36.256 ; 46.289,35.748 46.797,35.748 ; 46.289,36.256 46.289,36.764 ; 46.289,36.256 46.797,36.256 ; 46.289,36.764 46.289,37.272 ; 46.289,36.764 46.797,36.764 ; 46.289,37.272 46.289,37.78 ; 46.289,37.272 46.797,37.272 ; 46.289,37.78 46.289,38.288 ; 46.289,37.78 46.797,37.78 ; 46.289,38.288 46.289,38.796 ; 46.289,38.288 46.797,38.288 ; 46.289,38.796 46.289,39.304 ; 46.289,38.796 46.797,38.796 ; 46.289,39.304 46.289,39.812 ; 46.289,39.304 46.797,39.304 ; 46.289,39.812 46.289,40.32 ; 46.289,39.812 46.797,39.812 ; 46.289,40.32 46.289,40.828 ; 46.289,40.32 46.797,40.32 ; 46.289,40.828 46.289,41.336 ; 46.289,40.828 46.797,40.828 ; 46.289,41.336 46.289,41.844 ; 46.289,41.336 46.797,41.336 ; 46.289,41.844 46.289,42.352 ; 46.289,41.844 46.797,41.844 ; 46.289,46.838 46.289,46.924 ; 46.289,46.838 46.797,46.838 ; 46.289,46.924 46.289,47.432 ; 46.289,46.924 46.797,46.924 ; 46.289,47.432 46.289,47.94 ; 46.289,47.432 46.797,47.432 ; 46.289,47.94 46.289,48.448 ; 46.289,47.94 46.797,47.94 ; 46.289,48.448 46.289,48.956 ; 46.289,48.448 46.797,48.448 ; 46.289,48.956 46.289,49.112 46.289,49.464 ; 46.289,48.956 46.797,48.956 ; 46.289,49.464 46.289,49.972 ; 46.289,49.464 46.797,49.464 ; 46.289,49.972 46.289,50.48 ; 46.289,49.972 46.797,49.972 ; 46.289,50.48 46.797,50.48 ; 46.289,50.48 46.289,50.497 ; 46.289,50.497 ccw(c45.337,51.456) 46.292,50.5 cw(c45.337,51.456) 46.289,50.497 ; 46.289,54.32 46.289,54.544 ; 46.289,54.32 46.513,54.544 ; 46.289,54.544 46.289,55.052 ; 46.289,54.544 46.513,54.544 ; 46.289,55.052 46.289,55.56 ; 46.289,55.052 46.797,55.052 ; 46.289,55.56 46.289,56.032 ; 46.289,55.56 46.797,55.56 ; 46.289,56.032 46.797,56.029 ; 46.382,24.064 46.412,24.094 cw(c47.729,24.397) 46.389,24.572 ; 46.389,24.572 cw(c47.729,24.397) 46.562,25.08 ; 46.513,54.544 46.797,54.828 ; 46.78,50.988 47.288,51.496 ; 46.78,50.988 46.797,50.988 ; 46.797,20.889 46.797,21.016 ; 46.797,20.889 47.305,20.889 ; 46.797,21.016 46.797,21.524 ; 46.797,21.016 47.305,21.016 ; 46.797,21.524 46.797,21.692 ; 46.797,21.524 47.305,21.524 ; 46.797,21.692 47.305,21.692 ; 46.797,25.588 46.797,26.096 ; 46.797,25.588 47.09,25.588 ; 46.797,26.096 46.797,26.604 ; 46.797,26.096 47.305,26.096 ; 46.797,26.604 46.797,27.112 ; 46.797,26.604 47.305,26.604 ; 46.797,27.112 46.797,27.145 ; 46.797,27.112 47.305,27.112 ; 46.797,27.145 47.305,27.145 ; 46.797,29.111 46.797,29.144 ; 46.797,29.144 46.797,29.289 ; 46.797,34.282 47.305,34.282 ; 46.797,34.282 46.797,34.732 ; 46.797,34.732 46.797,35.24 ; 46.797,34.732 47.305,34.732 ; 46.797,35.24 46.797,35.748 ; 46.797,35.24 47.305,35.24 ; 46.797,35.748 46.797,36.256 ; 46.797,35.748 47.305,35.748 ; 46.797,36.256 47.305,36.256 ; 46.797,36.256 46.797,36.764 ; 46.797,36.764 47.305,36.764 ; 46.797,36.764 46.797,37.272 ; 46.797,37.272 46.797,37.78 ; 46.797,37.272 47.305,37.272 ; 46.797,37.78 47.305,37.78 ; 46.797,37.78 46.797,38.288 ; 46.797,38.288 46.797,38.796 ; 46.797,38.288 47.305,38.288 ; 46.797,38.796 46.797,39.304 ; 46.797,38.796 47.305,38.796 ; 46.797,39.304 46.797,39.812 ; 46.797,39.304 47.305,39.304 ; 46.797,39.812 46.797,40.32 ; 46.797,39.812 47.305,39.812 ; 46.797,40.32 47.305,40.32 ; 46.797,40.32 46.797,40.828 ; 46.797,40.828 46.797,41.336 ; 46.797,40.828 47.305,40.828 ; 46.797,41.336 47.305,41.336 ; 46.797,41.336 46.797,41.844 ; 46.797,41.844 47.305,41.844 ; 46.797,41.844 46.797,42.187 ; 46.797,42.187 ccw(c46.979,43.576) 46.808,42.185 ccw(c46.979,43.576) 47.305,42.213 ; 46.797,46.838 46.797,46.924 ; 46.797,46.838 47.305,46.838 ; 46.797,46.924 46.797,47.432 ; 46.797,46.924 47.305,46.924 ; 46.797,47.432 46.797,47.94 ; 46.797,47.432 47.305,47.432 ; 46.797,47.94 46.797,48.448 ; 46.797,47.94 47.305,47.94 ; 46.797,48.448 46.797,48.956 ; 46.797,48.448 47.305,48.448 ; 46.797,48.956 46.797,49.112 46.797,49.464 ; 46.797,48.956 47.305,48.956 ; 46.797,49.464 46.797,49.972 ; 46.797,49.464 47.305,49.464 ; 46.797,49.972 46.797,50.48 ; 46.797,49.972 47.305,49.972 ; 46.797,50.48 47.305,50.48 ; 46.797,50.48 46.797,50.988 ; 46.797,50.988 47.305,50.988 ; 46.797,54.828 46.797,55.052 ; 46.797,54.828 47.021,55.052 ; 46.797,55.052 46.797,55.56 ; 46.797,55.052 47.021,55.052 ; 46.797,55.56 46.797,56.029 ; 46.797,55.56 47.305,55.56 ; 46.797,56.029 47.305,56.025 ; 47.09,25.588 cw(c47.729,24.397) 47.094,25.59 cw(c47.729,24.397) 47.305,25.68 ; 47.288,51.496 47.305,51.496 ; 47.288,51.496 47.305,51.513 ; 47.305,20.889 47.305,21.016 ; 47.305,20.889 47.813,20.889 ; 47.305,21.016 47.305,21.524 ; 47.305,21.016 47.813,21.016 ; 47.305,21.524 47.305,21.692 ; 47.305,21.524 47.813,21.524 ; 47.305,21.692 47.813,21.692 ; 47.305,25.68 cw(c47.729,24.397) 47.311,25.682 cw(c47.729,24.397) 47.813,25.746 ; 47.305,25.68 47.305,26.096 ; 47.305,26.096 47.305,26.604 ; 47.305,26.096 47.813,26.096 ; 47.305,26.604 47.305,27.112 ; 47.305,26.604 47.813,26.604 ; 47.305,27.112 47.305,27.145 ; 47.305,27.112 47.813,27.112 ; 47.305,27.145 47.813,27.145 ; 47.305,34.282 47.414,34.282 47.414,34.224 ; 47.305,34.282 47.305,34.732 ; 47.305,34.732 47.305,35.24 ; 47.305,34.732 47.813,34.732 ; 47.305,35.24 47.305,35.748 ; 47.305,35.24 47.813,35.24 ; 47.305,35.748 47.305,36.256 ; 47.305,35.748 47.813,35.748 ; 47.305,36.256 47.813,36.256 ; 47.305,36.256 47.305,36.764 ; 47.305,36.764 47.813,36.764 ; 47.305,36.764 47.305,37.272 ; 47.305,37.272 47.305,37.78 ; 47.305,37.272 47.813,37.272 ; 47.305,37.78 47.305,38.288 ; 47.305,37.78 47.813,37.78 ; 47.305,38.288 47.305,38.796 ; 47.305,38.288 47.813,38.288 ; 47.305,38.796 47.305,39.304 ; 47.305,38.796 47.813,38.796 ; 47.305,39.304 47.305,39.812 ; 47.305,39.304 47.813,39.304 ; 47.305,39.812 47.305,40.32 ; 47.305,39.812 47.813,39.812 ; 47.305,40.32 47.305,40.828 ; 47.305,40.32 47.813,40.32 ; 47.305,40.828 47.305,41.336 ; 47.305,40.828 47.813,40.828 ; 47.305,41.336 47.305,41.844 ; 47.305,41.336 47.813,41.336 ; 47.305,41.844 47.813,41.844 ; 47.305,41.844 47.305,42.213 ; 47.305,42.213 ccw(c46.979,43.576) 47.661,42.352 ; 47.305,46.838 47.813,46.838 ; 47.305,46.838 47.305,46.924 ; 47.305,46.924 47.813,46.924 ; 47.305,46.924 47.305,47.432 ; 47.305,47.432 47.813,47.432 ; 47.305,47.432 47.305,47.94 ; 47.305,47.94 47.813,47.94 ; 47.305,47.94 47.305,48.448 ; 47.305,48.448 47.813,48.448 ; 47.305,48.448 47.305,48.956 ; 47.305,48.956 47.813,48.956 ; 47.305,48.956 47.305,49.112 47.305,49.464 ; 47.305,49.464 47.813,49.464 ; 47.305,49.464 47.305,49.972 ; 47.305,49.972 47.813,49.972 ; 47.305,49.972 47.305,50.48 ; 47.305,50.48 47.813,50.48 ; 47.305,50.48 47.305,50.988 ; 47.305,50.988 47.305,51.496 ; 47.305,50.988 47.813,50.988 ; 47.305,51.496 47.305,51.513 ; 47.305,51.496 47.813,51.496 ; 47.305,51.513 47.796,52.004 ; 47.305,55.328 ccw(c48.171,54.29) 47.215,55.246 cw(c48.171,54.29) 47.305,55.328 ; 47.305,55.328 cw(c48.171,54.29) 47.708,55.56 ; 47.305,55.328 cw(c48.171,54.29) 47.708,55.56 ; 47.305,55.328 47.305,55.56 ; 47.305,55.56 47.305,56.025 ; 47.305,55.56 47.708,55.56 ; 47.305,56.025 47.813,56.022 ; 47.414,34.224 47.414,34.155 47.813,34.155 ; 47.414,34.224 47.813,34.224 ; 47.661,42.352 ccw(c46.979,43.576) 47.813,42.45 ; 47.661,42.352 47.813,42.352 ; 47.708,55.56 cw(c48.171,54.29) 47.813,55.593 ; 47.708,55.56 cw(c48.171,54.29) 47.813,55.593 ; 47.796,52.004 47.813,52.004 ; 47.796,52.004 47.813,52.021 ; 47.813,20.889 48.321,20.889 ; 47.813,20.889 47.813,21.016 ; 47.813,21.016 48.321,21.016 ; 47.813,21.016 47.813,21.524 ; 47.813,21.524 47.813,21.692 ; 47.813,21.524 48.321,21.524 ; 47.813,21.692 48.321,21.692 ; 47.813,25.746 cw(c47.729,24.397) 48.321,25.612 ; 47.813,25.746 47.813,26.096 ; 47.813,26.096 47.813,26.604 ; 47.813,26.096 48.321,26.096 ; 47.813,26.604 47.813,27.112 ; 47.813,26.604 48.321,26.604 ; 47.813,27.112 47.813,27.145 ; 47.813,27.112 48.321,27.112 ; 47.813,27.145 48.321,27.145 ; 47.813,34.155 48.321,34.155 ; 47.813,34.155 47.813,34.224 ; 47.813,34.224 48.321,34.224 ; 47.813,34.224 47.813,34.732 ; 47.813,34.732 47.813,35.24 ; 47.813,34.732 48.321,34.732 ; 47.813,35.24 47.813,35.748 ; 47.813,35.24 48.321,35.24 ; 47.813,35.748 47.813,36.256 ; 47.813,35.748 48.321,35.748 ; 47.813,36.256 48.321,36.256 ; 47.813,36.256 47.813,36.764 ; 47.813,36.764 48.321,36.764 ; 47.813,36.764 47.813,37.272 ; 47.813,37.272 47.813,37.78 ; 47.813,37.272 48.321,37.272 ; 47.813,37.78 48.321,37.78 ; 47.813,37.78 47.813,38.288 ; 47.813,38.288 47.813,38.796 ; 47.813,38.288 48.321,38.288 ; 47.813,38.796 47.813,39.304 ; 47.813,38.796 48.321,38.796 ; 47.813,39.304 47.813,39.812 ; 47.813,39.304 48.321,39.304 ; 47.813,39.812 47.813,40.32 ; 47.813,39.812 48.321,39.812 ; 47.813,40.32 48.321,40.32 ; 47.813,40.32 47.813,40.828 ; 47.813,40.828 47.813,41.336 ; 47.813,40.828 48.321,40.828 ; 47.813,41.336 48.321,41.336 ; 47.813,41.336 47.813,41.844 ; 47.813,41.844 47.813,42.352 ; 47.813,41.844 48.321,41.844 ; 47.813,42.352 48.321,42.352 ; 47.813,42.352 47.813,42.45 ; 47.813,42.45 ccw(c46.979,43.576) 47.823,42.457 ccw(c46.979,43.576) 48.184,42.86 ; 47.813,46.838 47.813,46.924 ; 47.813,46.838 48.321,46.838 ; 47.813,46.924 47.813,47.432 ; 47.813,46.924 48.321,46.924 ; 47.813,47.432 47.813,47.94 ; 47.813,47.432 48.321,47.432 ; 47.813,47.94 47.813,48.448 ; 47.813,47.94 48.321,47.94 ; 47.813,48.448 47.813,48.956 ; 47.813,48.448 48.321,48.448 ; 47.813,48.956 47.813,49.112 47.813,49.464 ; 47.813,48.956 48.321,48.956 ; 47.813,49.464 47.813,49.972 ; 47.813,49.464 48.321,49.464 ; 47.813,49.972 47.813,50.48 ; 47.813,49.972 48.321,49.972 ; 47.813,50.48 47.813,50.988 ; 47.813,50.48 48.321,50.48 ; 47.813,50.988 47.813,51.496 ; 47.813,50.988 48.321,50.988 ; 47.813,51.496 47.813,52.004 ; 47.813,51.496 48.321,51.496 ; 47.813,52.004 48.321,52.004 ; 47.813,52.004 47.813,52.021 ; 47.813,52.021 48.304,52.512 ; 47.813,55.593 cw(c48.171,54.29) 47.821,55.596 ; 47.813,55.593 cw(c48.171,54.29) 47.821,55.596 ; 47.813,55.593 47.813,56.022 ; 47.813,56.022 48.321,56.019 ; 47.821,55.596 cw(c48.171,54.29) 48.171,55.642 ; 47.821,55.596 cw(c48.171,54.29) 48.171,55.642 ; 48.153,44.384 48.321,44.384 ; 48.153,44.384 48.153,44.635 48.321,44.635 ; 48.171,55.642 48.321,55.642 ; 48.184,42.86 ccw(c46.979,43.576) 48.321,43.172 ; 48.184,42.86 48.321,42.86 ; 48.304,52.512 48.321,52.512 ; 48.304,52.512 48.321,52.529 ; 48.321,20.889 48.829,20.889 ; 48.321,20.889 48.321,21.016 ; 48.321,21.016 48.829,21.016 ; 48.321,21.016 48.321,21.524 ; 48.321,21.524 48.321,21.692 ; 48.321,21.524 48.829,21.524 ; 48.321,21.692 48.829,21.692 ; 48.321,25.612 48.321,26.096 ; 48.321,26.096 48.321,26.604 ; 48.321,26.096 48.829,26.096 ; 48.321,26.604 48.321,27.112 ; 48.321,26.604 48.829,26.604 ; 48.321,27.112 48.321,27.145 ; 48.321,27.112 48.829,27.112 ; 48.321,27.145 48.575,27.145 ; 48.321,34.155 48.415,34.155 48.484,34.224 ; 48.321,34.155 48.321,34.224 ; 48.321,34.224 48.484,34.224 ; 48.321,34.224 48.321,34.732 ; 48.321,34.732 48.321,35.24 ; 48.321,34.732 48.829,34.732 ; 48.321,35.24 48.321,35.748 ; 48.321,35.24 48.829,35.24 ; 48.321,35.748 48.321,36.256 ; 48.321,35.748 48.829,35.748 ; 48.321,36.256 48.829,36.256 ; 48.321,36.256 48.321,36.764 ; 48.321,36.764 48.829,36.764 ; 48.321,36.764 48.321,37.272 ; 48.321,37.272 48.321,37.78 ; 48.321,37.272 48.829,37.272 ; 48.321,37.78 48.829,37.78 ; 48.321,37.78 48.321,38.288 ; 48.321,38.288 48.321,38.796 ; 48.321,38.288 48.829,38.288 ; 48.321,38.796 48.321,39.304 ; 48.321,38.796 48.829,38.796 ; 48.321,39.304 48.321,39.812 ; 48.321,39.304 48.829,39.304 ; 48.321,39.812 48.321,40.32 ; 48.321,39.812 48.829,39.812 ; 48.321,40.32 48.829,40.32 ; 48.321,40.32 48.321,40.828 ; 48.321,40.828 48.321,41.336 ; 48.321,40.828 48.829,40.828 ; 48.321,41.336 48.829,41.336 ; 48.321,41.336 48.321,41.844 ; 48.321,41.844 48.321,42.352 ; 48.321,41.844 48.829,41.844 ; 48.321,42.352 48.321,42.86 ; 48.321,42.352 48.829,42.352 ; 48.321,42.86 48.829,42.86 ; 48.321,42.86 48.321,43.172 ; 48.321,43.172 ccw(c46.979,43.576) 48.365,43.368 ; 48.321,43.981 cw(c46.979,43.576) 48.348,43.876 ; 48.321,43.981 48.321,44.384 ; 48.321,44.384 48.829,44.384 ; 48.321,44.384 48.321,44.635 ; 48.321,44.635 48.829,44.635 ; 48.321,46.838 48.829,46.838 ; 48.321,46.838 48.321,46.924 ; 48.321,46.924 48.829,46.924 ; 48.321,46.924 48.321,47.432 ; 48.321,47.432 48.829,47.432 ; 48.321,47.432 48.321,47.94 ; 48.321,47.94 48.829,47.94 ; 48.321,47.94 48.321,48.448 ; 48.321,48.448 48.829,48.448 ; 48.321,48.448 48.321,48.956 ; 48.321,48.956 48.829,48.956 ; 48.321,48.956 48.321,49.112 48.321,49.464 ; 48.321,49.464 48.829,49.464 ; 48.321,49.464 48.321,49.972 ; 48.321,49.972 48.829,49.972 ; 48.321,49.972 48.321,50.48 ; 48.321,50.48 48.829,50.48 ; 48.321,50.48 48.321,50.988 ; 48.321,50.988 48.829,50.988 ; 48.321,50.988 48.321,51.496 ; 48.321,51.496 48.321,52.004 ; 48.321,51.496 48.829,51.496 ; 48.321,52.004 48.829,52.004 ; 48.321,52.004 48.321,52.512 ; 48.321,52.512 48.829,52.512 ; 48.321,52.512 48.321,52.529 ; 48.321,52.529 48.73,52.938 48.829,52.938 ; 48.321,55.642 48.829,55.642 ; 48.321,55.642 48.321,56.019 ; 48.321,56.019 48.829,56.015 ; 48.348,43.876 cw(c46.979,43.576) 48.381,43.576 cw(c46.979,43.576) 48.365,43.368 ; 48.348,43.876 48.829,43.876 ; 48.365,43.368 48.829,43.368 ; 48.484,34.224 48.829,34.569 ; 48.575,27.145 ccw(c48.575,27.874) 48.824,27.189 ; 48.575,27.145 ccw(c48.575,27.874) 48.824,27.189 ; 48.824,27.189 ccw(c48.575,27.874) 48.829,27.191 ; 48.824,27.189 ccw(c48.575,27.874) 48.829,27.191 ; 48.829,20.889 48.829,21.016 ; 48.829,20.889 49.337,20.889 ; 48.829,21.016 48.829,21.524 ; 48.829,21.016 49.337,21.016 ; 48.829,21.524 48.829,21.692 ; 48.829,21.524 49.337,21.524 ; 48.829,21.692 49.337,21.692 ; 48.829,25.182 cw(c47.729,24.397) 48.895,25.08 ; 48.829,25.182 48.829,25.588 ; 48.829,25.588 48.829,26.096 ; 48.829,25.588 49.337,25.588 ; 48.829,26.096 48.829,26.604 ; 48.829,26.096 49.337,26.096 ; 48.829,26.604 48.829,27.112 ; 48.829,26.604 49.337,26.604 ; 48.829,27.112 49.337,27.112 ; 48.829,27.112 48.829,27.191 ; 48.829,27.191 ccw(c48.575,27.874) 49.09,27.359 ; 48.829,27.191 ccw(c48.575,27.874) 49.09,27.359 ; 48.829,34.569 48.829,34.732 ; 48.829,34.569 48.992,34.732 ; 48.829,34.732 48.829,35.24 ; 48.829,34.732 48.992,34.732 ; 48.829,35.24 48.829,35.748 ; 48.829,35.24 49.337,35.24 ; 48.829,35.748 48.829,36.256 ; 48.829,35.748 49.337,35.748 ; 48.829,36.256 48.829,36.764 ; 48.829,36.256 49.337,36.256 ; 48.829,36.764 48.829,37.272 ; 48.829,36.764 49.337,36.764 ; 48.829,37.272 48.829,37.78 ; 48.829,37.272 49.337,37.272 ; 48.829,37.78 48.829,38.288 ; 48.829,37.78 49.337,37.78 ; 48.829,38.288 48.829,38.796 ; 48.829,38.288 49.337,38.288 ; 48.829,38.796 48.829,39.304 ; 48.829,38.796 49.337,38.796 ; 48.829,39.304 48.829,39.812 ; 48.829,39.304 49.337,39.304 ; 48.829,39.812 48.829,40.32 ; 48.829,39.812 49.337,39.812 ; 48.829,40.32 48.829,40.828 ; 48.829,40.32 49.337,40.32 ; 48.829,40.828 48.829,41.336 ; 48.829,40.828 49.337,40.828 ; 48.829,41.336 48.829,41.844 ; 48.829,41.336 49.337,41.336 ; 48.829,41.844 48.829,42.352 ; 48.829,41.844 49.337,41.844 ; 48.829,42.352 48.829,42.86 ; 48.829,42.352 49.337,42.352 ; 48.829,42.86 48.829,43.368 ; 48.829,42.86 49.337,42.86 ; 48.829,43.368 48.829,43.876 ; 48.829,43.368 49.337,43.368 ; 48.829,43.876 48.829,44.384 ; 48.829,43.876 49.337,43.876 ; 48.829,44.384 48.829,44.635 ; 48.829,44.384 49.337,44.384 ; 48.829,44.635 49.337,44.635 ; 48.829,46.838 48.829,46.924 ; 48.829,46.838 49.337,46.838 ; 48.829,46.924 48.829,47.432 ; 48.829,46.924 49.337,46.924 ; 48.829,47.432 48.829,47.94 ; 48.829,47.432 49.337,47.432 ; 48.829,47.94 48.829,48.448 ; 48.829,47.94 49.337,47.94 ; 48.829,48.448 48.829,48.956 ; 48.829,48.448 49.337,48.448 ; 48.829,48.956 48.829,49.112 48.829,49.464 ; 48.829,48.956 49.337,48.956 ; 48.829,49.464 48.829,49.972 ; 48.829,49.464 49.337,49.464 ; 48.829,49.972 48.829,50.48 ; 48.829,49.972 49.337,49.972 ; 48.829,50.48 49.337,50.48 ; 48.829,50.48 48.829,50.988 ; 48.829,50.988 49.337,50.988 ; 48.829,50.988 48.829,51.496 ; 48.829,51.496 48.829,52.004 ; 48.829,51.496 49.337,51.496 ; 48.829,52.004 49.337,52.004 ; 48.829,52.004 48.829,52.512 ; 48.829,52.512 48.829,52.938 ; 48.829,52.512 49.337,52.512 ; 48.829,52.938 49.337,52.938 ; 48.829,55.642 48.829,56.015 ; 48.829,55.642 49.337,55.642 ; 48.829,56.015 49.337,56.012 ; 48.895,25.08 cw(c47.729,24.397) 48.899,25.073 cw(c47.729,24.397) 48.999,24.86 cw(c50.269,24.397) 49.098,25.073 cw(c50.269,24.397) 49.102,25.08 ; 48.895,25.08 49.102,25.08 ; 48.992,34.732 49.337,35.077 ; 49.09,27.359 49.351,27.62 ; 49.337,20.889 49.337,21.016 ; 49.337,20.889 49.845,20.889 ; 49.337,21.016 49.337,21.524 ; 49.337,21.016 49.845,21.016 ; 49.337,21.524 49.337,21.692 ; 49.337,21.524 49.845,21.524 ; 49.337,21.692 49.845,21.692 ; 49.337,25.588 49.337,26.096 ; 49.337,25.588 49.63,25.588 ; 49.337,26.096 49.337,26.604 ; 49.337,26.096 49.845,26.096 ; 49.337,26.604 49.337,27.112 ; 49.337,26.604 49.845,26.604 ; 49.337,27.112 49.845,27.112 ; 49.337,35.077 49.337,35.24 ; 49.337,35.077 49.5,35.24 ; 49.337,35.24 49.337,35.748 ; 49.337,35.24 49.5,35.24 ; 49.337,35.748 49.337,36.256 ; 49.337,35.748 49.845,35.748 ; 49.337,36.256 49.337,36.764 ; 49.337,36.256 49.845,36.256 ; 49.337,36.764 49.337,37.272 ; 49.337,36.764 49.845,36.764 ; 49.337,37.272 49.337,37.78 ; 49.337,37.272 49.845,37.272 ; 49.337,37.78 49.337,38.288 ; 49.337,37.78 49.845,37.78 ; 49.337,38.288 49.337,38.796 ; 49.337,38.288 49.845,38.288 ; 49.337,38.796 49.337,39.304 ; 49.337,38.796 49.845,38.796 ; 49.337,39.304 49.337,39.812 ; 49.337,39.304 49.845,39.304 ; 49.337,39.812 49.337,40.32 ; 49.337,39.812 49.845,39.812 ; 49.337,40.32 49.337,40.828 ; 49.337,40.32 49.845,40.32 ; 49.337,40.828 49.337,41.336 ; 49.337,40.828 49.845,40.828 ; 49.337,41.336 49.337,41.844 ; 49.337,41.336 49.845,41.336 ; 49.337,41.844 49.337,42.352 ; 49.337,41.844 49.845,41.844 ; 49.337,42.352 49.337,42.86 ; 49.337,42.352 49.845,42.352 ; 49.337,42.86 49.337,43.368 ; 49.337,42.86 49.845,42.86 ; 49.337,43.368 49.337,43.876 ; 49.337,43.368 49.845,43.368 ; 49.337,43.876 49.337,44.384 ; 49.337,43.876 49.845,43.876 ; 49.337,44.384 49.337,44.635 ; 49.337,44.384 49.845,44.384 ; 49.337,44.635 49.845,44.635 ; 49.337,46.838 49.337,46.924 ; 49.337,46.838 49.845,46.838 ; 49.337,46.924 49.337,47.432 ; 49.337,46.924 49.845,46.924 ; 49.337,47.432 49.337,47.94 ; 49.337,47.432 49.845,47.432 ; 49.337,47.94 49.337,48.448 ; 49.337,47.94 49.845,47.94 ; 49.337,48.448 49.337,48.956 ; 49.337,48.448 49.845,48.448 ; 49.337,48.956 49.337,49.112 49.337,49.464 ; 49.337,48.956 49.845,48.956 ; 49.337,49.464 49.337,49.972 ; 49.337,49.464 49.845,49.464 ; 49.337,49.972 49.337,50.48 ; 49.337,49.972 49.845,49.972 ; 49.337,50.48 49.337,50.988 ; 49.337,50.48 49.845,50.48 ; 49.337,50.988 49.337,51.496 ; 49.337,50.988 49.845,50.988 ; 49.337,51.496 49.337,52.004 ; 49.337,51.496 49.845,51.496 ; 49.337,52.004 49.337,52.512 ; 49.337,52.004 49.845,52.004 ; 49.337,52.512 49.337,52.938 ; 49.337,52.512 49.845,52.512 ; 49.337,52.938 49.845,52.938 ; 49.337,55.642 49.337,56.012 ; 49.337,55.642 49.845,55.642 ; 49.337,56.012 49.845,56.009 ; 49.351,27.62 49.845,28.114 ; 49.351,27.62 49.845,27.62 ; 49.446,32.7 R74.1@49.845,32.7 ; 49.446,32.7 49.446,33.124 49.529,33.208 ; 49.446,32.7 49.446,32.596 R74.1@49.845,32.596 ; 49.5,35.24 49.845,35.585 ; 49.529,33.208 R74.1@49.845,33.208 ; 49.529,33.208 49.725,33.404 50.037,33.716 ; 49.63,25.588 cw(c50.269,24.397) 49.634,25.59 cw(c50.269,24.397) 49.845,25.68 ; 49.845,20.889 49.845,21.016 ; 49.845,20.889 50.353,20.889 ; 49.845,21.016 49.845,21.524 ; 49.845,21.016 50.353,21.016 ; 49.845,21.524 49.845,21.692 ; 49.845,21.524 50.353,21.524 ; 49.845,21.692 50.353,21.692 ; 49.845,25.68 cw(c50.269,24.397) 50.353,25.746 ; 49.845,25.68 49.845,26.096 ; 49.845,26.096 49.845,26.604 ; 49.845,26.096 50.353,26.096 ; 49.845,26.604 49.845,27.112 ; 49.845,26.604 50.353,26.604 ; 49.845,27.112 50.353,27.112 ; 49.845,27.112 49.845,27.62 ; 49.845,27.62 49.845,28.114 ; 49.845,27.62 50.353,27.62 ; 49.845,28.114 49.859,28.128 ; R74.1@49.845,32.596 R74.1@49.845,32.7 ; R74.1@49.845,32.596 R74.1@50.353,32.596 ; R74.1@49.845,32.7 R74.1@50.353,32.7 ; R74.1@49.845,32.7 R74.1@49.845,33.208 ; R74.1@49.845,33.208 R74.1@50.353,33.208 ; 49.845,35.585 50.008,35.748 ; 49.845,35.585 49.845,35.748 ; 49.845,35.748 49.845,36.256 ; 49.845,35.748 50.008,35.748 ; 49.845,36.256 49.845,36.764 ; 49.845,36.256 50.353,36.256 ; 49.845,36.764 49.845,37.272 ; 49.845,36.764 50.353,36.764 ; 49.845,37.272 49.845,37.78 ; 49.845,37.272 50.353,37.272 ; 49.845,37.78 49.845,38.288 ; 49.845,37.78 50.353,37.78 ; 49.845,38.288 49.845,38.796 ; 49.845,38.288 50.353,38.288 ; 49.845,38.796 49.845,39.304 ; 49.845,38.796 50.353,38.796 ; 49.845,39.304 49.845,39.812 ; 49.845,39.304 50.353,39.304 ; 49.845,39.812 49.845,40.32 ; 49.845,39.812 50.353,39.812 ; 49.845,40.32 49.845,40.828 ; 49.845,40.32 50.353,40.32 ; 49.845,40.828 49.845,41.336 ; 49.845,40.828 50.353,40.828 ; 49.845,41.336 49.845,41.844 ; 49.845,41.336 50.353,41.336 ; 49.845,41.844 49.845,42.352 ; 49.845,41.844 50.353,41.844 ; 49.845,42.352 49.845,42.86 ; 49.845,42.352 50.353,42.352 ; 49.845,42.86 49.845,43.368 ; 49.845,42.86 50.353,42.86 ; 49.845,43.368 49.845,43.876 ; 49.845,43.368 50.353,43.368 ; 49.845,43.876 49.845,44.384 ; 49.845,43.876 50.353,43.876 ; 49.845,44.384 49.845,44.635 ; 49.845,44.384 50.353,44.384 ; 49.845,44.635 50.353,44.635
